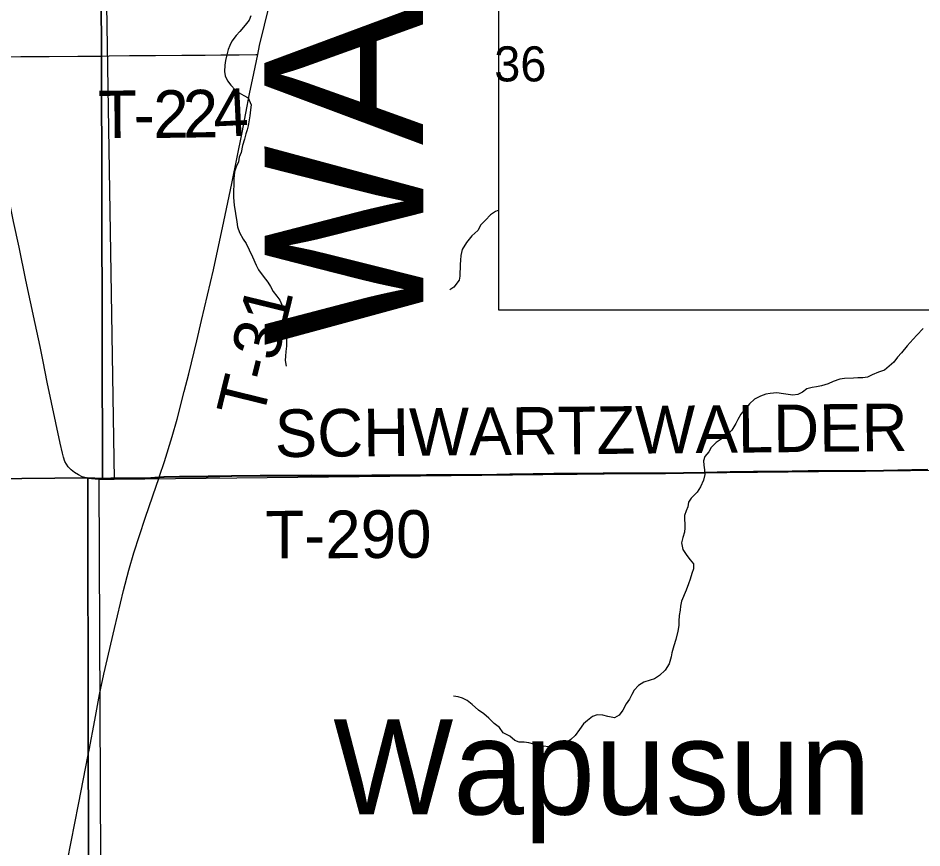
# Model space of a CAD drawing. Extents: x 0 to 34, y 0 to 22.
# Drawn here: x 2.529 to 3.608, y 17.938 to 18.929 of the extents above; entities that cross this region are included whole.
import ezdxf

# ---------------------------------------------------------------- set-up
doc = ezdxf.new("R2010")
doc.units = 0
for name, color, linetype in [('Default', 7, 'Continuous'), ('GM_X_County_Road', 7, 'Continuous'), ('GM_X_County_Text', 7, 'Continuous'), ('GM_X_Minor_Lake_Text', 7, 'Continuous'), ('GM_X_Minor_River', 7, 'Continuous'), ('GM_X_Section', 7, 'Continuous'), ('GM_X_Section_Text', 7, 'Continuous'), ('GM_X_Township_Road', 7, 'Continuous'), ('GM_X_Township_Road_Text', 7, 'Continuous'), ('SH_Cut_Line', 7, 'Continuous'), ('SH_Text', 7, 'Continuous')]:
    doc.layers.add(name, color=color, linetype=linetype)

msp = doc.modelspace()

# ---------------------------------------------------------------- linework, layer by layer
at = {"layer": 'Default'}
for points in [[(2.6032, 20.9), (2.1, 20.9), (2.1, 18.375), (2.6118, 18.3803), (2.6161, 18.3799), (2.6204, 18.3797), (2.6263, 18.3795), (2.6292, 18.3794), (2.6281, 18.8843), (2.6224, 19.9515), (2.6032, 20.8721)], [(2.1, 18.375), (2.1, 14.3539), (2.1651, 14.3567), (2.6607, 14.3625), (2.6434, 15.3487), (2.6428, 15.3713), (2.6388, 15.4856), (2.6332, 16.3685), (2.6231, 17.3771), (2.6129, 17.8818), (2.6122, 18.05), (2.6118, 18.3803)]]:
    msp.add_lwpolyline(points, close=True, dxfattribs=at)
for points in [[(2.6224, 19.9515), (2.6281, 18.8843), (2.6292, 18.3794), (2.6393, 18.3797), (2.6872, 18.3804), (2.6968, 18.3811), (2.7027, 18.3816), (2.7213, 18.3818), (2.7554, 18.3822), (2.7834, 18.3826), (2.8176, 18.383), (2.8795, 18.3834), (2.9231, 18.3831), (2.951, 18.3836), (2.9726, 18.3836), (2.9943, 18.3836), (3.0161, 18.3837), (3.0441, 18.3839), (3.1001, 18.3843), (3.1156, 18.3845), (3.128, 18.3848), (3.1435, 18.385), (3.1683, 18.3853), (3.1961, 18.3852), (3.2272, 18.3856), (3.264, 18.3858), (3.3012, 18.3859), (3.3229, 18.3862), (3.3477, 18.3867), (3.3788, 18.3873), (3.4067, 18.3876), (3.453, 18.3882), (3.4719, 18.3885), (3.4843, 18.3886), (3.5153, 18.3887), (3.5277, 18.3887), (3.54, 18.3887), (3.5618, 18.389), (3.5959, 18.3898), (3.6146, 18.3902)], [(3.6146, 18.3902), (3.5959, 18.3898), (3.5618, 18.389), (3.54, 18.3887), (3.5277, 18.3887), (3.5153, 18.3887), (3.4843, 18.3886), (3.4719, 18.3885), (3.453, 18.3882), (3.4067, 18.3876), (3.3788, 18.3873), (3.3477, 18.3867), (3.3229, 18.3862), (3.3012, 18.3859), (3.264, 18.3858), (3.2272, 18.3856), (3.1961, 18.3852), (3.1683, 18.3853), (3.1435, 18.385), (3.128, 18.3848), (3.1156, 18.3845), (3.1001, 18.3843), (3.0441, 18.3839), (3.0161, 18.3837), (2.9943, 18.3836), (2.9726, 18.3836), (2.951, 18.3836), (2.9231, 18.3831), (2.8795, 18.3834), (2.8176, 18.383), (2.7834, 18.3826), (2.7554, 18.3822), (2.7213, 18.3818), (2.7027, 18.3816), (2.6968, 18.3811), (2.6872, 18.3804), (2.6393, 18.3797), (2.6292, 18.3794), (2.6263, 18.3795), (2.6204, 18.3797), (2.6161, 18.3799), (2.6118, 18.3803), (2.6122, 18.05), (2.6129, 17.8818)]]:
    msp.add_lwpolyline(points, dxfattribs=at)
at = {"layer": 'GM_X_County_Road'}
for points in [[(2.612, 18.3797), (2.605, 18.3816), (2.6008, 18.3837), (2.5961, 18.3866), (2.5918, 18.3897), (2.5882, 18.3934), (2.5844, 18.3998), (2.5827, 18.4047), (2.5816, 18.4095), (2.5789, 18.4216), (2.5635, 18.4945), (2.5585, 18.5189), (2.5548, 18.5371), (2.5491, 18.5645), (2.5379, 18.6161), (2.5297, 18.6557), (2.5233, 18.6861), (2.5056, 18.7712), (2.5023, 18.7864), (2.4967, 18.8106), (2.4913, 18.8316), (2.4814, 18.8708), (2.4785, 18.8823)], [(2.6294, 18.3789), (2.6265, 18.379), (2.6206, 18.3791), (2.6163, 18.3793), (2.612, 18.3797)], [(2.5792, 17.8787), (2.5807, 17.8867), (2.5876, 17.9233), (2.6008, 17.9904), (2.6124, 18.0495)]]:
    msp.add_lwpolyline(points, dxfattribs=at)
at = {"layer": 'GM_X_Minor_River'}
for points in [[(2.8066, 18.9317), (2.8044, 18.9264), (2.7998, 18.9207), (2.7933, 18.9131), (2.7891, 18.9082), (2.7838, 18.9013), (2.7815, 18.8964), (2.7796, 18.8914), (2.7774, 18.8834), (2.7762, 18.8785), (2.7755, 18.8728), (2.7751, 18.8652), (2.7759, 18.8599), (2.7786, 18.8542), (2.7824, 18.8488), (2.7878, 18.8435), (2.7927, 18.8397), (2.7981, 18.8367), (2.8031, 18.8336), (2.8069, 18.8256), (2.8061, 18.8195), (2.8054, 18.8123), (2.8046, 18.8074), (2.8031, 18.8005), (2.802, 18.7956), (2.8005, 18.7907), (2.799, 18.7846), (2.7967, 18.777), (2.7948, 18.7686), (2.7925, 18.7629), (2.7918, 18.7576), (2.7888, 18.7515), (2.7869, 18.7454), (2.7861, 18.737), (2.7861, 18.7302), (2.7858, 18.7222), (2.7858, 18.715), (2.7866, 18.7055), (2.7881, 18.6956), (2.7897, 18.6857), (2.7905, 18.68), (2.7928, 18.6732), (2.7974, 18.6652), (2.8008, 18.6598), (2.8043, 18.6522), (2.8085, 18.6439), (2.8127, 18.634), (2.8158, 18.6283), (2.8211, 18.621), (2.8269, 18.6138), (2.8299, 18.6085), (2.833, 18.6028), (2.8376, 18.5971), (2.841, 18.5921), (2.8433, 18.5868), (2.846, 18.5815), (2.8472, 18.572), (2.8476, 18.5636), (2.8484, 18.5571), (2.8492, 18.5488), (2.8492, 18.5374), (2.8484, 18.5309), (2.8477, 18.5256), (2.8473, 18.5203), (2.8485, 18.5134)], [(3.1024, 18.6996), (3.0988, 18.6981), (3.0927, 18.6943), (3.0866, 18.6878), (3.0812, 18.6821), (3.0774, 18.6753), (3.0702, 18.6692), (3.0641, 18.6612), (3.0588, 18.6529), (3.0573, 18.6456), (3.0569, 18.6399), (3.0566, 18.635), (3.0562, 18.6209), (3.0551, 18.616), (3.049, 18.608), (3.044, 18.6046)], [(3.6093, 18.5586), (3.6017, 18.5507), (3.5972, 18.5457), (3.5903, 18.5377), (3.5835, 18.5294), (3.5785, 18.5241), (3.5743, 18.5184)], [(3.5743, 18.5184), (3.5686, 18.5134), (3.5629, 18.5089), (3.556, 18.5062), (3.5484, 18.5032), (3.5427, 18.5005), (3.5373, 18.4997), (3.5312, 18.4997), (3.5259, 18.499), (3.5152, 18.4986), (3.5099, 18.4979), (3.5019, 18.4952), (3.4958, 18.4925), (3.4878, 18.4899), (3.482, 18.4887), (3.4767, 18.488), (3.4702, 18.4865), (3.4653, 18.4823), (3.4595, 18.4796), (3.4538, 18.4789), (3.4424, 18.4804), (3.4344, 18.4815), (3.4267, 18.4808), (3.4214, 18.48), (3.4149, 18.4778), (3.408, 18.4743), (3.4019, 18.4686), (3.3966, 18.4622), (3.3917, 18.4561), (3.3879, 18.45), (3.3856, 18.4451), (3.3807, 18.4371), (3.3753, 18.4321), (3.3704, 18.428), (3.362, 18.4223), (3.3563, 18.4166), (3.3532, 18.4112), (3.3487, 18.4055), (3.3468, 18.4006), (3.3472, 18.3953), (3.3483, 18.3896), (3.3487, 18.3842), (3.3468, 18.3774), (3.3434, 18.3694), (3.3392, 18.3633), (3.3324, 18.3561), (3.329, 18.3512), (3.3282, 18.3458), (3.3263, 18.3409), (3.3244, 18.3352), (3.3245, 18.3207), (3.3241, 18.3154), (3.3222, 18.309), (3.3207, 18.3025), (3.3222, 18.2945), (3.3272, 18.2877), (3.331, 18.2823), (3.3352, 18.2774), (3.3349, 18.2717), (3.333, 18.266), (3.3311, 18.2591), (3.3292, 18.2538), (3.3262, 18.2462), (3.3208, 18.2329), (3.3193, 18.2272), (3.319, 18.2223), (3.3178, 18.2158), (3.3175, 18.2093), (3.3175, 18.204), (3.3164, 18.1972), (3.3141, 18.1873), (3.3114, 18.1797), (3.3092, 18.1713), (3.3084, 18.1664), (3.3058, 18.1584), (3.3012, 18.1508), (3.2943, 18.1443), (3.2886, 18.1405), (3.2833, 18.1386), (3.2757, 18.1363), (3.2692, 18.1322), (3.2642, 18.1268), (3.2612, 18.1215), (3.2585, 18.1162), (3.2547, 18.1105), (3.2506, 18.1029), (3.2464, 18.0968), (3.2407, 18.0938), (3.2326, 18.0953), (3.2269, 18.0968), (3.22, 18.0972), (3.2143, 18.0953), (3.2086, 18.0904), (3.2037, 18.0866), (3.1991, 18.0797), (3.1938, 18.0725), (3.1884, 18.0679), (3.182, 18.0634), (3.1759, 18.0603), (3.1679, 18.0585), (3.1617, 18.0592)], [(3.1617, 18.0592), (3.156, 18.06), (3.1495, 18.0619), (3.1442, 18.0623), (3.1385, 18.0638), (3.1327, 18.0649), (3.127, 18.0646), (3.1217, 18.0668), (3.1159, 18.0718), (3.1079, 18.076), (3.1033, 18.0821), (3.0972, 18.087), (3.0907, 18.0935), (3.0846, 18.0984), (3.0784, 18.103), (3.0708, 18.1098), (3.0647, 18.1144), (3.0593, 18.1171), (3.054, 18.119), (3.0483, 18.1197)]]:
    msp.add_lwpolyline(points, dxfattribs=at)
at = {"layer": 'GM_X_Section'}
for points in [[(3.619, 19.2976), (3.6177, 19.3939), (2.6269, 19.3875), (2.6434, 18.3786), (3.6306, 18.3893), (3.6281, 18.5805), (3.1024, 18.5805), (3.1024, 19.2976)], [(2.6434, 18.3786), (3.6306, 18.3893), (3.6458, 17.376), (2.6299, 17.3724), (2.6253, 18.3786)]]:
    msp.add_lwpolyline(points, close=True, dxfattribs=at)
at = {"layer": 'GM_X_Township_Road'}
for points in [[(2.8147, 18.8856), (2.8169, 18.8962), (2.8226, 18.9204), (2.8278, 18.9415), (2.8317, 18.9566), (2.8391, 18.9867), (2.843, 19.0049), (2.8508, 19.0413), (2.8573, 19.0717), (2.8619, 19.093), (2.8686, 19.1233), (2.871, 19.1355), (2.8713, 19.1369)], [(2.4785, 18.8823), (2.4844, 18.8824), (2.498, 18.8826), (2.5319, 18.883), (2.5658, 18.8832), (2.5998, 18.8835), (2.6283, 18.8837)], [(2.6283, 18.8837), (2.6375, 18.884), (2.6615, 18.8843), (2.6926, 18.8845), (2.7239, 18.8847), (2.7519, 18.8849), (2.7707, 18.885), (2.7924, 18.8852), (2.8124, 18.8856), (2.8147, 18.8856)], [(2.697, 18.3806), (2.6976, 18.3821), (2.7034, 18.3998), (2.7125, 18.4295), (2.7184, 18.4504), (2.727, 18.4834), (2.7323, 18.5045), (2.7419, 18.5437), (2.7477, 18.5679), (2.7619, 18.6284), (2.7743, 18.6861), (2.7838, 18.7317), (2.7961, 18.7926), (2.805, 18.8384), (2.81, 18.8627), (2.8147, 18.8856)], [(2.697, 18.3806), (2.7029, 18.3811), (2.7215, 18.3813), (2.7557, 18.3816), (2.7836, 18.3821), (2.8178, 18.3825), (2.8797, 18.3828), (2.9233, 18.3826), (2.9512, 18.383), (2.9728, 18.383), (2.9945, 18.3831), (3.0163, 18.3832), (3.0443, 18.3834), (3.1003, 18.3837), (3.1158, 18.3839), (3.1282, 18.3842), (3.1437, 18.3844), (3.1685, 18.3848), (3.1963, 18.3846), (3.2274, 18.385), (3.2642, 18.3852), (3.3015, 18.3853), (3.3231, 18.3857), (3.3479, 18.3861), (3.379, 18.3868), (3.4069, 18.387), (3.4532, 18.3876), (3.4721, 18.3879), (3.4845, 18.3881), (3.5155, 18.3881), (3.5279, 18.3881), (3.5402, 18.3882), (3.562, 18.3885), (3.5961, 18.3892), (3.6148, 18.3897)], [(2.612, 18.3797), (2.6163, 18.3793), (2.6206, 18.3791), (2.6265, 18.379), (2.6294, 18.3789)], [(2.6124, 18.0495), (2.6133, 18.0552), (2.6201, 18.0911), (2.6259, 18.1216), (2.6311, 18.1459), (2.6436, 18.2004), (2.6545, 18.2458), (2.6607, 18.2699), (2.6669, 18.2907), (2.6805, 18.3321), (2.6895, 18.3586), (2.697, 18.3806)], [(2.6294, 18.3789), (2.6395, 18.3791), (2.6874, 18.3798), (2.697, 18.3806)]]:
    msp.add_lwpolyline(points, dxfattribs=at)
at = {"layer": 'SH_Cut_Line'}
msp.add_lwpolyline([(2.6032, 20.9), (2.1, 20.9), (2.1, 14.3539), (2.1651, 14.3567), (2.6607, 14.3625), (2.6434, 15.3487), (2.6428, 15.3713), (2.6388, 15.4856), (2.6332, 16.3685), (2.6231, 17.3771), (2.6129, 17.8818), (2.6122, 18.05), (2.6118, 18.3803), (2.6161, 18.3799), (2.6204, 18.3797), (2.6263, 18.3795), (2.6292, 18.3794), (2.6281, 18.8843), (2.6224, 19.9515), (2.6032, 20.8721)], close=True, dxfattribs=at)
msp.add_lwpolyline([(8.9, 20.9), (2.6032, 20.9), (2.6032, 20.8721), (2.6224, 19.9515), (2.6281, 18.8843), (2.6292, 18.3794), (2.6263, 18.3795), (2.6204, 18.3797), (2.6161, 18.3799), (2.6118, 18.3803), (2.6122, 18.05), (2.6129, 17.8818), (2.6231, 17.3771), (2.6332, 16.3685)], dxfattribs=at)
at = {"layer": 'SH_Text'}
msp.add_lwpolyline([(3.1024, 19.2976), (5.3223, 19.2976), (5.3223, 18.5805), (3.1024, 18.5805)], close=True, dxfattribs=at)

# ---------------------------------------------------------------- texts
at = {"layer": 'GM_X_County_Text'}
msp.add_text('WAYNE COUNTY', height=0.189394, rotation=90.0755, dxfattribs=at).set_placement((3.0125, 18.5381))
at = {"layer": 'GM_X_Minor_Lake_Text'}
msp.add_text('Wapusun ', height=0.11366, rotation=359.9698, dxfattribs=at).set_placement((2.9048, 17.9785))
at = {"layer": 'GM_X_Section_Text'}
msp.add_text('36', height=0.04186, rotation=0, dxfattribs=at).set_placement((3.0971, 18.8534))
at = {"layer": 'GM_X_Township_Road_Text'}
for s, height, rotation, p in [('T', 0.0568, 0.2829, (2.6242, 18.7856)), ('2', 0.0568, 0.4356, (2.6902, 18.7859)), ('2', 0.0568, 0.9493, (2.7258, 18.7862)), ('4', 0.0568, 2.7858, (2.7628, 18.7868)), ('-', 0.0568, 0.3008, (2.6667, 18.7858)), ('T-31', 0.05682, 76.2189, (2.8204, 18.4483)), ('SCHWARTZWALDER', 0.056818, 0.5567, (2.8353, 18.4049)), ('T-290', 0.05682, 0.2812, (2.8238, 18.2839))]:
    msp.add_text(s, height=height, rotation=rotation, dxfattribs=at).set_placement(p)

doc.saveas('drawing.dxf')
